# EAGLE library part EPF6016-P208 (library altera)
EPF6016 FLEX 6000 family
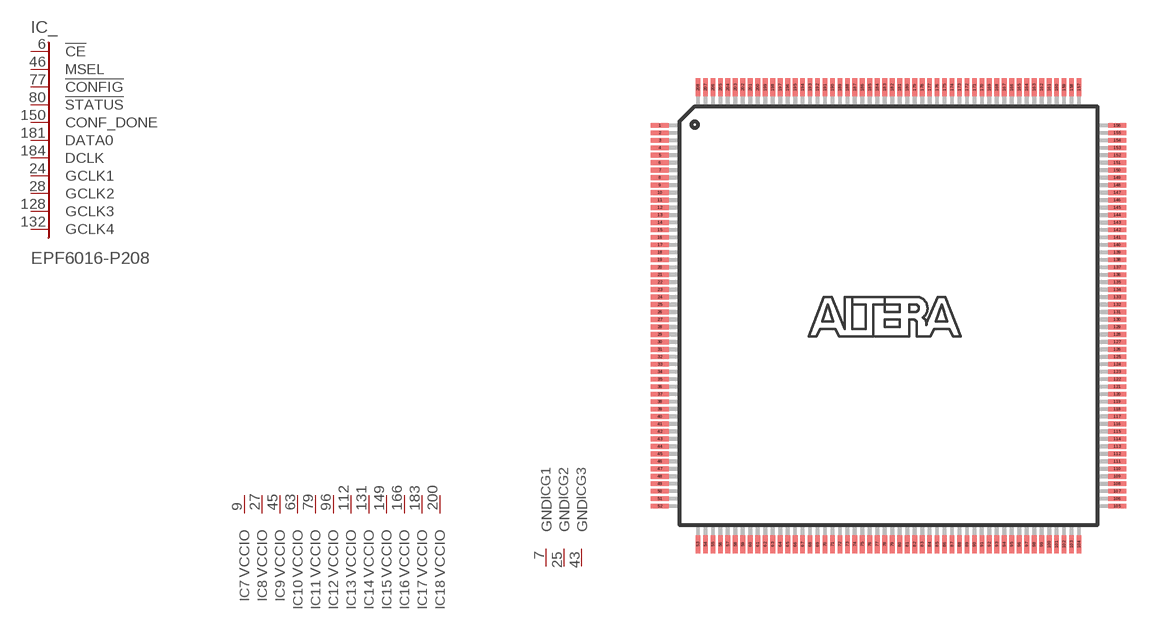
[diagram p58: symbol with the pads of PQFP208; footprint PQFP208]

Designator prefix IC; gates _=6016CONT 7=VCCIO 8=VCCIO 9=VCCIO 10=VCCIO 11=VCCIO 12=VCCIO 13=VCCIO 14=VCCIO 15=VCCIO 16=VCCIO 17=VCCIO 18=VCCIO G1=GND G2=GND G3=GND G4=GND G5=GND G6=GND G7=GND G8=GND G9=GND G10=GND G11=GND G12=GND -A=A15-18 -C=C16-18 -D=D16-18 -E=E16-19 -F=F16-19 -G=IO54-2 -H=IO94-3 -I=IO134-3 -J=IO174-2 -K=IO222-2 -B=B16-19 1=VCCINT 2=VCCINT 3=VCCINT 4=VCCINT 5=VCCINT 6=VCCINT

## EPF6016-P208 (MPN: EPF6016AQC208-3N; OC_FARNELL: 1549398; OC_NEWARK: 51R9156)  [PQFP208]
1  -A:IOA1
2  -A:IOA3
3  -A:IOA4
4  -B:IOB1
5  -B:IOB2
6  _:!CE  in
7  G1:GND  pwr
8  1:VCC  pwr
9  7:VCCIO  pwr
10  -B:IOB4
11  -B:IOB5
12  -B:IOB6
13  -B:IOB7
14  -B:IOB8
15  -B:IOB9
16  -C:IOC1
17  -C:IOC2
18  -C:IOC3
19  -C:IOC4
20  -C:IOC5
21  -C:IOC6
22  -C:IOC7
23  -C:IOC8
24  _:GCLK1
25  G2:GND  pwr
26  2:VCC  pwr
27  8:VCCIO  pwr
28  _:GCLK2
29  -D:IOD1
30  -D:IOD3
31  -D:IOD4
32  -D:IOD5
33  -D:IOD6
34  -D:IOD7
35  -D:IOD8
36  -D:IOD9
37  -E:IOE2
38  -E:IOE3
39  -E:IOE4
40  -E:IOE5
41  -E:IOE6
42  -E:IOE7
43  G3:GND  pwr
44  3:VCC  pwr
45  9:VCCIO  pwr
46  _:MSEL  in
47  -E:IOE9
48  -F:IOF1
49  -F:IOF2
50  -F:IOF3
51  -F:IOF4
52  -F:IOF5
53  -F:IOF7
54  -F:IOF8
55  -F:IOF9
56  -F:IOF10
57  -G:IO11
58  -G:IO21
59  -G:IO22
60  -G:IO31
61  -G:IO32
62  G4:GND  pwr
63  10:VCCIO  pwr
64  -G:IO41
65  -G:IO51
66  -G:IO52
67  -H:IO61
68  -H:IO71
69  -H:IO72
70  -H:IO81
71  -H:IO82
72  -H:IO91
73  -I:IO101
74  -I:IO102
75  -I:IO111
76  -I:IO112
77  _:!CONFIG  in
78  G5:GND  pwr
79  11:VCCIO  pwr
80  _:!STATUS  in
81  -I:IO121
82  -I:IO122
83  -I:IO132
84  -J:IO141
85  -J:IO142
86  -J:IO151
87  -J:IO152
88  -J:IO161
89  -J:IO162
90  -J:IO172
91  -K:IO181
92  -K:IO182
93  -K:IO191
94  -K:IO192
95  G6:GND  pwr
96  12:VCCIO  pwr
97  -K:IO202
98  -K:IO211
99  -K:IO212
100  -K:IO221
101  -F:IOF11
102  -F:IOF12
103  -F:IOF13
104  -F:IOF14
105  -F:IOF15
106  -F:IOF17
107  -F:IOF18
108  -E:IOE11
109  -E:IOE12
110  G7:GND  pwr
111  4:VCC  pwr
112  13:VCCIO  pwr
113  -E:IOE13
114  -E:IOE14
115  -E:IOE15
116  -E:IOE16
117  -E:IOE17
118  -E:IOE18
119  -E:IOE19
120  -D:IOD11
121  -D:IOD12
122  -D:IOD13
123  -D:IOD14
124  -D:IOD15
125  -D:IOD16
126  -D:IOD17
127  -D:IOD18
128  _:GCLK3
129  G8:GND  pwr
130  5:VCC  pwr
131  14:VCCIO  pwr
132  _:GCLK4
133  -C:IOC10
134  -C:IOC11
135  -C:IOC12
136  -C:IOC13
137  -C:IOC14
138  -C:IOC16
139  -C:IOC17
140  -C:IOC18
141  -B:IOB10
142  -B:IOB11
143  -B:IOB12
144  -B:IOB14
145  -B:IOB15
146  -B:IOB16
147  G9:GND  pwr
148  6:VCC  pwr
149  15:VCCIO  pwr
150  _:CONF_DONE  in
151  -B:IOB17
152  -B:IOB18
153  -A:IOA6
154  -A:IOA7
155  -A:IOA8
156  -A:IOA9
157  -A:IOA11
158  -A:IOA12
159  -A:IOA13
160  -A:IOA14
161  -K:IO222
162  -K:IO214
163  -K:IO203
164  -K:IO204
165  G10:GND  pwr
166  16:VCCIO  pwr
167  -K:IO193
168  -K:IO194
169  -K:IO183
170  -K:IO184
171  -J:IO173
172  -J:IO174
173  -J:IO163
174  -J:IO164
175  -J:IO153
176  -J:IO154
177  -J:IO143
178  -I:IO133
179  -I:IO134
180  -I:IO123
181  _:DATA0
182  G11:GND  pwr
183  17:VCCIO  pwr
184  _:DCLK  in
185  -I:IO113
186  -I:IO114
187  -I:IO104
188  -H:IO93
189  -H:IO94
190  -H:IO83
191  -H:IO73
192  -H:IO74
193  -H:IO63
194  -H:IO64
195  -G:IO53
196  -G:IO54
197  -G:IO43
198  -G:IO44
199  G12:GND  pwr
200  18:VCCIO  pwr
201  -G:IO34
202  -G:IO23
203  -G:IO24
204  -G:IO12
205  -A:IOA15
206  -A:IOA16
207  -A:IOA17
208  -A:IOA18

## Footprint PQFP208 (pad centres in mm)
Plastic Quad Flat Pack
smd 1.2 x 0.32: 1 -15.3,12.75; 2 -15.3,12.25; 3 -15.3,11.75; 4 -15.3,11.25; 5 -15.3,10.75; 6 -15.3,10.25; 7 -15.3,9.75; 8 -15.3,9.25; 9 -15.3,8.75; 10 -15.3,8.25; 11 -15.3,7.75; 12 -15.3,7.25; 13 -15.3,6.75; 14 -15.3,6.25; 15 -15.3,5.75; 16 -15.3,5.25; 17 -15.3,4.75; 18 -15.3,4.25; 19 -15.3,3.75; 20 -15.3,3.25; 21 -15.3,2.75; 22 -15.3,2.25; 23 -15.3,1.75; 24 -15.3,1.25; 25 -15.3,0.75; 26 -15.3,0.25; 27 -15.3,-0.25; 28 -15.3,-0.75; 29 -15.3,-1.25; 30 -15.3,-1.75; 31 -15.3,-2.25; 32 -15.3,-2.75; 33 -15.3,-3.25; 34 -15.3,-3.75; 35 -15.3,-4.25; 36 -15.3,-4.75; 37 -15.3,-5.25; 38 -15.3,-5.75; 39 -15.3,-6.25; 40 -15.3,-6.75; 41 -15.3,-7.25; 42 -15.3,-7.75; 43 -15.3,-8.25; 44 -15.3,-8.75; 45 -15.3,-9.25; 46 -15.3,-9.75; 47 -15.3,-10.25; 48 -15.3,-10.75; 49 -15.3,-11.25; 50 -15.3,-11.75; 51 -15.3,-12.25; 52 -15.3,-12.75; 105 15.3,-12.75; 106 15.3,-12.25; 107 15.3,-11.75; 108 15.3,-11.25; 109 15.3,-10.75; 110 15.3,-10.25; 111 15.3,-9.75; 112 15.3,-9.25; 113 15.3,-8.75; 114 15.3,-8.25; 115 15.3,-7.75; 116 15.3,-7.25; 117 15.3,-6.75; 118 15.3,-6.25; 119 15.3,-5.75; 120 15.3,-5.25; 121 15.3,-4.75; 122 15.3,-4.25; 123 15.3,-3.75; 124 15.3,-3.25; 125 15.3,-2.75; 126 15.3,-2.25; 127 15.3,-1.75; 128 15.3,-1.25; 129 15.3,-0.75; 130 15.3,-0.25; 131 15.3,0.25; 132 15.3,0.75; 133 15.3,1.25; 134 15.3,1.75; 135 15.3,2.25; 136 15.3,2.75; 137 15.3,3.25; 138 15.3,3.75; 139 15.3,4.25; 140 15.3,4.75; 141 15.3,5.25; 142 15.3,5.75; 143 15.3,6.25; 144 15.3,6.75; 145 15.3,7.25; 146 15.3,7.75; 147 15.3,8.25; 148 15.3,8.75; 149 15.3,9.25; 150 15.3,9.75; 151 15.3,10.25; 152 15.3,10.75; 153 15.3,11.25; 154 15.3,11.75; 155 15.3,12.25; 156 15.3,12.75
smd 0.32 x 1.2: 53 -12.75,-15.3; 54 -12.25,-15.3; 55 -11.75,-15.3; 56 -11.25,-15.3; 57 -10.75,-15.3; 58 -10.25,-15.3; 59 -9.75,-15.3; 60 -9.25,-15.3; 61 -8.75,-15.3; 62 -8.25,-15.3; 63 -7.75,-15.3; 64 -7.25,-15.3; 65 -6.75,-15.3; 66 -6.25,-15.3; 67 -5.75,-15.3; 68 -5.25,-15.3; 69 -4.75,-15.3; 70 -4.25,-15.3; 71 -3.75,-15.3; 72 -3.25,-15.3; 73 -2.75,-15.3; 74 -2.25,-15.3; 75 -1.75,-15.3; 76 -1.25,-15.3; 77 -0.75,-15.3; 78 -0.25,-15.3; 79 0.25,-15.3; 80 0.75,-15.3; 81 1.25,-15.3; 82 1.75,-15.3; 83 2.25,-15.3; 84 2.75,-15.3; 85 3.25,-15.3; 86 3.75,-15.3; 87 4.25,-15.3; 88 4.75,-15.3; 89 5.25,-15.3; 90 5.75,-15.3; 91 6.25,-15.3; 92 6.75,-15.3; 93 7.25,-15.3; 94 7.75,-15.3; 95 8.25,-15.3; 96 8.75,-15.3; 97 9.25,-15.3; 98 9.75,-15.3; 99 10.25,-15.3; 100 10.75,-15.3; 101 11.25,-15.3; 102 11.75,-15.3; 103 12.25,-15.3; 104 12.75,-15.3; 157 12.75,15.3; 158 12.25,15.3; 159 11.75,15.3; 160 11.25,15.3; 161 10.75,15.3; 162 10.25,15.3; 163 9.75,15.3; 164 9.25,15.3; 165 8.75,15.3; 166 8.25,15.3; 167 7.75,15.3; 168 7.25,15.3; 169 6.75,15.3; 170 6.25,15.3; 171 5.75,15.3; 172 5.25,15.3; 173 4.75,15.3; 174 4.25,15.3; 175 3.75,15.3; 176 3.25,15.3; 177 2.75,15.3; 178 2.25,15.3; 179 1.75,15.3; 180 1.25,15.3; 181 0.75,15.3; 182 0.25,15.3; 183 -0.25,15.3; 184 -0.75,15.3; 185 -1.25,15.3; 186 -1.75,15.3; 187 -2.25,15.3; 188 -2.75,15.3; 189 -3.25,15.3; 190 -3.75,15.3; 191 -4.25,15.3; 192 -4.75,15.3; 193 -5.25,15.3; 194 -5.75,15.3; 195 -6.25,15.3; 196 -6.75,15.3; 197 -7.25,15.3; 198 -7.75,15.3; 199 -8.25,15.3; 200 -8.75,15.3; 201 -9.25,15.3; 202 -9.75,15.3; 203 -10.25,15.3; 204 -10.75,15.3; 205 -11.25,15.3; 206 -11.75,15.3; 207 -12.25,15.3; 208 -12.75,15.3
